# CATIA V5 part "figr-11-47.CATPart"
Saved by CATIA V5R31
Part number: Part1
Bounding box of the stored display mesh (mm): x -171.181 to 0, y -220 to 0, z -11.432 to 46.691
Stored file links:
  D:\PROJECTS\Project 2021\US EDITION\CATIA V5 6R 2021\Resources\Part Files\c11_catia_v5_6r2021_prt\figr-11-47.CATPart
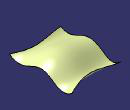
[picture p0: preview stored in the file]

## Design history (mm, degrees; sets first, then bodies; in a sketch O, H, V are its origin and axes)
Set1
  Sweep1: type Unspec, Profile Sketch2, Guide Sketch1
Body1 (main body)
  Sketch1 on yz-plane, origin (0, 0, 0), H (0, 1, 0), V (0, 0, 1)
    spline S1 through (0, 0) (-40, -10) (-100, 20) (-170, 0) (-220, 10)
    point P1 (0, 0)
    coincidence: P1 O
  Sketch2 on zx-plane, origin (0, 0, 0), H (-1, 0, 0), V (0, 0, 1)
    spline S1 through (0, 0) (60, 30) (121.1814, 19.9844) (171.1814, 9.9844)
    point P1 (0, 0)
    coincidence: P1 O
